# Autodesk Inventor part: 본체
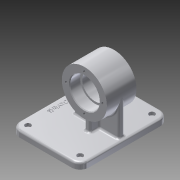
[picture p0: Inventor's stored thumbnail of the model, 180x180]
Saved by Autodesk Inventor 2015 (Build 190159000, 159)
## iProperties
Created: 2019-09
Part Number: 본체
Material: 알루미늄 6061
Document SubType Name: Modeling
Designer: CAD-08
Density: 2.7 g/cm^3
Appearance: 알루미늄 - 평지
Mass: 554.62 g
Surface Area: 495.884 cm^2
Volume: 205.415 cm^3
Author: CAD-08
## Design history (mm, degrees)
sketch "스케치1"
  geometry: C1 r 32 at (0, 0); 1 further point
  constraints: 1 centre point, 1 coincident
  dimensions: "d0" = 64 diameter of C1
extrude "돌출1" new body sketch "스케치1" distance "d1" = 42; taper "d2" = 0 deg
sketch "스케치2"
  geometry: C1 r 32 at (0, 0) reference
hole "구멍1" sketch "스케치2" at (0, 0) diameter "d3" = 36; stored, may be unused: countersink angle "d7" = 90 deg, drill point angle "d9" = 118 deg; dims "d4" = 6, "d5" = 4, "d6" = 2, "d8" = 8
sketch "스케치3"
  geometry: C1 r 18 at (0, 0) reference
hole "구멍2" sketch "스케치3" at (0, 0) diameter "d10" = 42; stored, may be unused: countersink angle "d14" = 90 deg, drill point angle "d16" = 0 deg; dims "d11" = 6, "d12" = 4, "d13" = 2, "d15" = 15
sketch "스케치4"
  geometry: C1 r 18 at (0, 0) reference
hole "구멍3" sketch "스케치4" at (0, 0) diameter "d17" = 42; stored, may be unused: countersink angle "d21" = 90 deg, drill point angle "d23" = 0 deg; dims "d18" = 6, "d19" = 4, "d20" = 2, "d22" = 15
node "작업 평면1"
sketch "스케치6"
  geometry: L1 (36, -42)-(-62, -42); L2 (-62, -42)-(-62, 84); L3 (-62, 84)-(36, 84); L4 (36, 84)-(36, -42); L5 (36, -42)-(-62, 84); L6 (-62, -42)-(36, 84); 2 further points
  constraints: 12 end point, 2 midpoint, 2 parallel, 1 horizontal, 1 perpendicular
  dimensions: "d30" = 126 distance of L3.end L1.start; "d31" = 98 distance of L2.end L3.end; "d32" = 21 vertical distance of point (0, 0) point (-13, 21); "d33" = 36 distance from line of point (0, 0) L4
extrude "돌출3" join sketch "스케치6" distance "d34" = 9; taper "d35" = 0 deg
sketch "스케치7"
  geometry: L1 (36, 84)-(-62, 84) reference; L2 (-62, 84)-(-62, -42) reference; L3 (32, 25)-(-32, 25); L4 (-32, 25)-(-32, 17); L5 (-32, 17)-(32, 17); L6 (32, 17)-(32, 25); L7 (32, 25)-(-32, 17); L8 (-32, 25)-(32, 17); L9 (4, 38)-(-4, 38); L10 (-4, 38)-(-4, 4); L11 (-4, 4)-(4, 4); L12 (4, 4)-(4, 38); L13 (4, 38)-(-4, 4); L14 (-4, 38)-(4, 4); 3 further points
  constraints: 24 end point, 4 midpoint, 4 parallel, 2 horizontal, 2 perpendicular
  dimensions: "d36" = 8 distance of L3.end L4.end; "d37" = 8 distance of L9.start L9.end; "d38" = 62 distance from line of L2 point (0, 21); "d39" = 62 distance from line of L2 point (0, 21); "d40" = 34 distance of L9.end L10.end; "d41" = 63 distance from line of L1 point (0, 21); "d42" = 63 distance from line of L1 point (0, 21); "d43" = 64 distance of L3.start L3.end
extrude "돌출4" join sketch "스케치7" stored distance "d44" = 9; taper "d45" = 0 deg
fillet "모깎기1" dims "d46" = 12
chamfer "모따기1" distance "d47" = 1; stored, may be unused: second distance "d48" = 2, angle "d49" = 45 deg
fillet "모깎기2" dims "d50" = 0.3
sketch "스케치8"
  geometry: C1 r 32 at (0, 0) reference; 1 further point
  constraints: 1 vertical alignment
  dimensions: "d51" = 26 distance of C1.centre point (0, 26)
hole "구멍4" sketch "스케치8" at (0, 26) diameter "d52" = 3.242; stored, may be unused: countersink angle "d56" = 90 deg, drill point angle "d58" = 118 deg; dims "d53" = 8, "d54" = 4, "d55" = 2, "d57" = 10
sketch "스케치9"
  geometry: C1 r 32 at (0, 0) reference; 1 further point
  constraints: 1 vertical alignment
  dimensions: "d62" = 26 distance of point (0, -26) C1.centre
hole "구멍5" sketch "스케치9" at (0, -26) diameter "d63" = 3.242; stored, may be unused: countersink angle "d67" = 90 deg, drill point angle "d69" = 118 deg; dims "d64" = 8, "d65" = 4, "d66" = 2, "d68" = 10
sketch "스케치10"
  geometry: A1 r 12 centre (-50, 72) between (-50, 84) and (-62, 72) reference; A2 r 12 centre (-50, -30) between (-62, -30) and (-50, -42) reference; A3 r 12 centre (24, -30) between (24, -42) and (36, -30) reference; A4 r 12 centre (24, 72) between (36, 72) and (24, 84) reference; 1 further point
hole "구멍6" sketch "스케치10" at (-50, -30), (24, -30), (24, 72), (-50, 72) diameter "d73" = 4.5; stored, may be unused: countersink angle "d77" = 90 deg, drill point angle "d79" = 118 deg; dims "d74" = 8, "d75" = 8, "d76" = 4.4, "d78" = 10
sketch "스케치11"
  geometry: L1 (-62, 72)-(-62, -30) reference; L2 (24, 84)-(-50, 84) reference; 2 further points
  constraints: 1 other
  dimensions: "d80" = 10 distance from line of L1 point (-52, 21); "d81" = 63 distance from line of L2 point (-52, 21)
feature "엠보싱1" sketch "스케치11" dims "d1" = 42, "d2" = 0, "d82" = 0.5, "d83" = 0
fillet "모깎기3" dims "d84" = 3
fillet "모깎기4" dims "d85" = 3
fillet "모깎기5" dims "d86" = 3
fillet "모깎기6" dims "d87" = 3
fillet "모깎기7" dims "d88" = 3
node "솔리드1"
pattern_circular "원형 패턴1" dims angle "d60" = 360 deg
pattern_circular "원형 패턴2" dims angle "d71" = 360 deg
other parameters: "d24" = -59
